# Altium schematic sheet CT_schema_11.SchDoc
size 278 x 170 mm
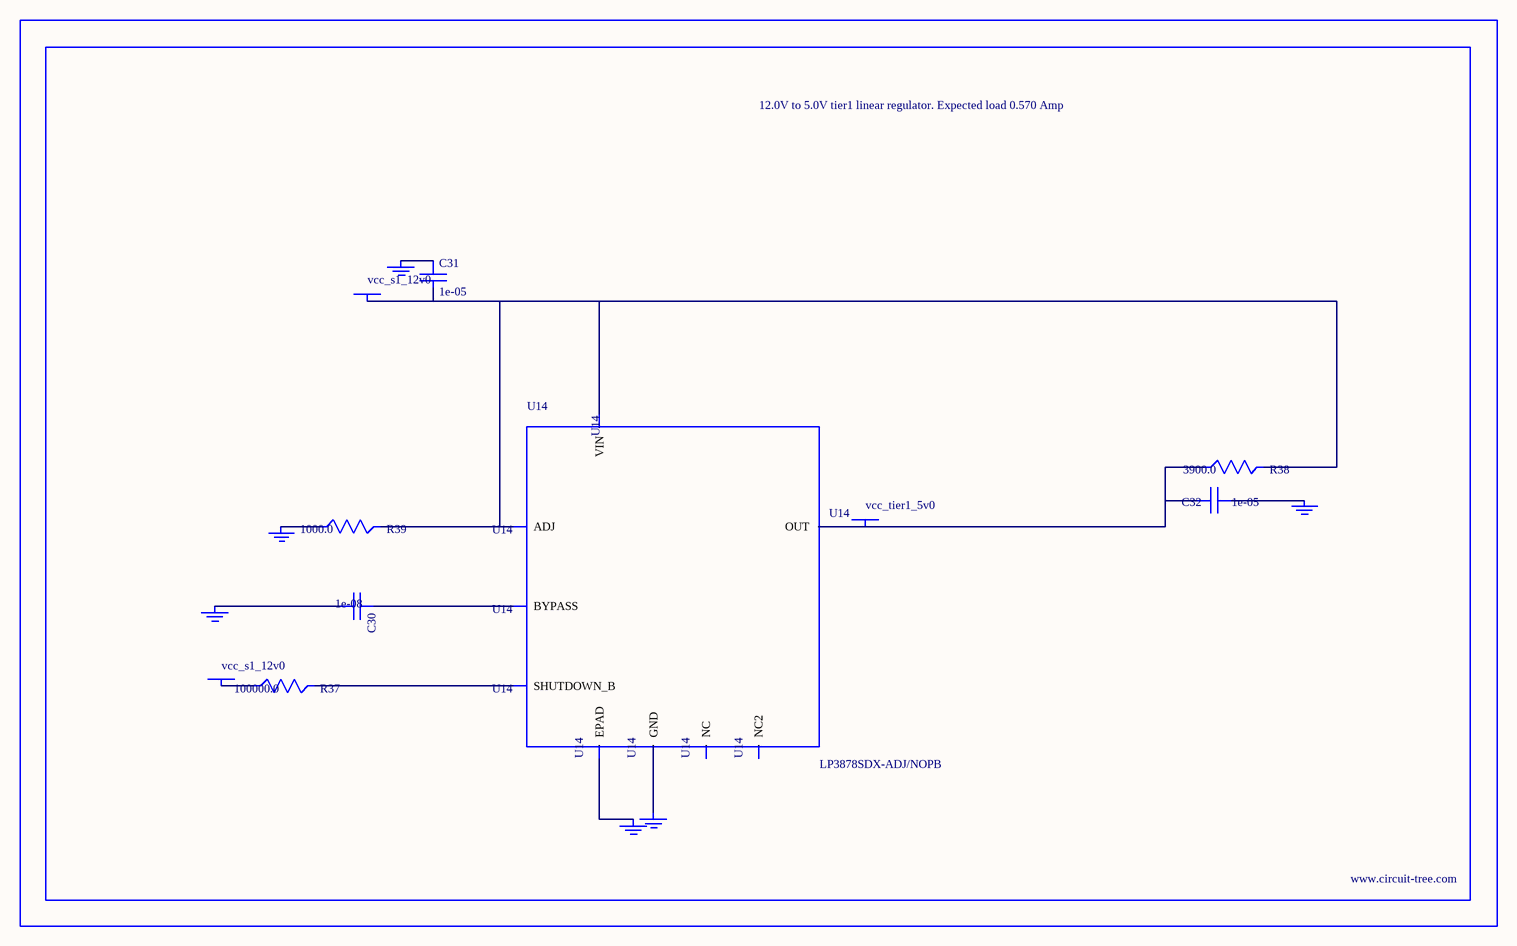
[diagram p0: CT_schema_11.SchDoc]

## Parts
BORDER10  (no value)
C30  1e-08  [C0402]
C31  1e-05  [C1210]
C32  1e-05  [C1210]
GND_INSTANCE_10_0  (no value)
GND_INSTANCE_10_1  (no value)
GND_INSTANCE_10_2  (no value)
GND_INSTANCE_10_3  (no value)
GND_INSTANCE_10_4  (no value)
GND_INSTANCE_10_5  (no value)
POWER_INSTANCE_10_0  vcc_s1_12v0
POWER_INSTANCE_10_1  vcc_s1_12v0
POWER_INSTANCE_10_2  vcc_tier1_5v0
R37  100000.0  [R0603]
R38  3900.0  [R0603]
R39  1000.0  [R0603]
U14  LP3878SDX-ADJ/NOPB  [WSON-8]

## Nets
NetC30_1: C30.1 U14.1(BYPASS)
NetC30_2: C30.2 GND_INSTANCE_10_0.0(GND)
NetC31_1: C31.1 GND_INSTANCE_10_1.0(GND)
NetC31_2: C31.2 POWER_INSTANCE_10_0.0(PWR) R38.2 R39.2 U14.4(VIN) U14.6(ADJ)
NetC32_1: C32.1 GND_INSTANCE_10_2.0(GND)
NetC32_2: C32.2 POWER_INSTANCE_10_2.0(PWR) R38.1 U14.5(OUT)
NetGND_INSTANCE_10_3_0: GND_INSTANCE_10_3.0(GND) R39.1
NetGND_INSTANCE_10_4_0: GND_INSTANCE_10_4.0(GND) U14.PAD(EPAD)
NetGND_INSTANCE_10_5_0: GND_INSTANCE_10_5.0(GND) U14.3(GND)
NetPOWER_INSTANCE_10_1_0: POWER_INSTANCE_10_1.0(PWR) R37.1
NetR37_2: R37.2 U14.8(SHUTDOWN_B)

Not connected (* = marked no-connect by the designer): U14 2(NC) 7(NC2)

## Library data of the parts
BORDER10 = BORDER_PAGE10
C30 = C0402C103K3RAC
C31 = C1210C106K5PACTU
C32 = GRM32DR61E106MA12L
GND_INSTANCE_10_0-GND_INSTANCE_10_5 = GND
POWER_INSTANCE_10_0-POWER_INSTANCE_10_2 = PWR
R37 = RC0603JR-07100KL
R38 = RC0603JR-073K9L
R39 = RC0603JR-071KL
